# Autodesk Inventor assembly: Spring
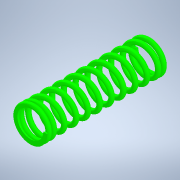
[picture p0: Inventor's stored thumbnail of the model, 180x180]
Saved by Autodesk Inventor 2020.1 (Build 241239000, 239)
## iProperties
Created: 2020-04
Part Number: Spring
Document SubType Name: Assembly
Designer: Safarabadi
Author: Safarabadi
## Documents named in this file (2)
- C:\Users\Safarabadi\Desktop\00-GrabCAD\00-Mask\MPB - Face mask ear loop welding machine - (3D & 2D)\MPB-14-00-00-00 (V2)\Spring.iam
- C:\Users\Safarabadi\Desktop\00-GrabCAD\00-Mask\MPB - Face mask ear loop welding machine - (3D & 2D)\MPB-14-00-00-00 (V2)\Compress Spring11.ipt
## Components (1 placed, 1 different names)
1. Compress Spring1:1 — Mate:1, Flush:1
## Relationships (2: Mate 1, Flush 1)
- Mate:1: Compress Spring1:1
- Flush:1: Compress Spring1:1
